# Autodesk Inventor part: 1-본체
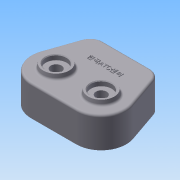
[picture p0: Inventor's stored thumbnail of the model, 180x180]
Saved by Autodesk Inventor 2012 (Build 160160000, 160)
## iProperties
Created: 2014-12
Part Number: 1-본체
Material: 알루미늄-6061
Document SubType Name: Modeling
Designer: Owner
Density: 2.71 g/cm^3
Mass: 613.304 g
Surface Area: 666.548 cm^2
Volume: 226.311 cm^3
Author: Owner
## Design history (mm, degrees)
sketch "스케치1"
  geometry: L1 (-47, 36)-(47, 36); L2 (-32.527, -32.527)-(0, 0); L3 (32.527, -32.527)-(0, 0); L4 (-32.527, -68.527)-(32.527, -68.527); L5 (-47, 36)-(-66.565, -20.803); L6 (47, 36)-(66.565, -20.803); A1 r 46 centre (0, 0) between (-32.527, -32.527) and (32.527, -32.527); A2 r 36 centre (-32.527, -32.527) between (-32.527, -68.527) and (-66.565, -20.803); A3 r 36 centre (32.527, -32.527) between (32.527, -68.527) and (66.565, -20.803); 2 further points
  constraints: 12 end point, 6 point on circle, 3 centre point, 3 tangent, 1 coincident, 1 equal radius, 1 horizontal, 1 horizontal alignment, 1 midpoint, 1 parallel, 1 vertical alignment
  dimensions: "d0" = 46 radius of A1; "d1" = 94 distance of L1.start L1.end; "d2" = 36 vertical distance of point (0, 0) L1.end; "d3" = 36 radius of A2; "d4" = 90 deg angle of L3 L2
extrude "돌출1" new body sketch "스케치1" distance "d5" = 44; taper "d6" = 0 deg
sketch "스케치2"
  geometry: C1 r 20 at (-32.527, -32.527); C2 r 20 at (32.527, -32.527); A1 r 36 centre (32.527, -32.527) between (32.527, -68.527) and (66.565, -20.803) reference; A2 r 36 centre (-32.527, -32.527) between (-66.565, -20.803) and (-32.527, -68.527) reference; 1 further point
  constraints: 2 centre point, 2 coincident, 1 equal radius
  dimensions: "d7" = 40 diameter of C2
extrude "돌출2" join sketch "스케치2" distance "d8" = 7; taper "d9" = -10 deg
sketch "스케치3"
  geometry: L1 (47, 36)-(66.565, -20.803) reference; L2 (-47, 36)-(47, 36) reference; L3 (-66.565, -20.803)-(-47, 36) reference; L4 (32.527, -68.527)-(-32.527, -68.527) reference; L5 (-43.434, 31)-(43.434, 31); L6 (43.434, 31)-(61.837, -22.432); L7 (-43.434, 31)-(-61.837, -22.432); L8 (-32.527, -63.527)-(32.527, -63.527); A1 r 36 centre (32.527, -32.527) between (32.527, -68.527) and (66.565, -20.803) reference; A2 r 36 centre (-32.527, -32.527) between (-66.565, -20.803) and (-32.527, -68.527) reference; A3 r 31 centre (-32.527, -32.527) between (-61.837, -22.432) and (-32.527, -63.527); A4 r 31 centre (32.527, -32.527) between (32.527, -63.527) and (61.837, -22.432); 1 further point
  constraints: 8 end point, 4 point on circle, 4 tangent, 3 parallel, 2 centre point, 2 coincident, 1 equal radius
  dimensions: "d10" = 31 radius of A3; "d12" = 5 distance between parallel lines of L2 L5
extrude "돌출3" cut sketch "스케치3" distance "d13" = 34; taper "d14" = 0 deg
sketch "스케치4"
  geometry: C1 r 24 at (0, 0); C2 r 24 at (-32.527, -32.527); C3 r 24 at (32.527, -32.527); A1 r 31 centre (-32.527, -32.527) between (-61.837, -22.432) and (-32.527, -63.527) reference; A2 r 31 centre (32.527, -32.527) between (32.527, -63.527) and (61.837, -22.432) reference; 1 further point
  constraints: 3 centre point, 3 coincident, 2 equal radius
  dimensions: "d15" = 48 diameter of C1
extrude "돌출4" join sketch "스케치4" distance "d16" = 11; taper "d17" = 0 deg
hole "구멍1" diameter "d20" = 15.5; stored, may be unused: countersink angle "d24" = 90 deg, drill point angle "d26" = 118 deg; dims "d18" = 10, "d19" = 10, "d21" = 6, "d22" = 30, "d23" = 7, "d25" = 8
hole "구멍2" diameter "d29" = 15.5; stored, may be unused: countersink angle "d33" = 90 deg, drill point angle "d35" = 118 deg; dims "d27" = 10, "d28" = 10, "d30" = 6, "d31" = 30, "d32" = 7, "d34" = 8
hole "구멍3" diameter "d38" = 20; stored, may be unused: countersink angle "d42" = 90 deg, drill point angle "d44" = 0 deg; dims "d39" = 6, "d40" = 40, "d41" = 12, "d43" = 15, "d45" = 10, "d46" = 10
hole "구멍4" diameter "d49" = 35; stored, may be unused: countersink angle "d53" = 90 deg, drill point angle "d55" = 0 deg; dims "d47" = 10, "d48" = 10, "d50" = 6, "d51" = 30, "d52" = 7, "d54" = 11
hole "구멍5" diameter "d58" = 35; stored, may be unused: countersink angle "d62" = 90 deg, drill point angle "d64" = 0 deg; dims "d56" = 10, "d57" = 10, "d59" = 6, "d60" = 30, "d61" = 7, "d63" = 11
sketch "스케치5"
  geometry: L1 (-47, 36)-(47, 36) reference; 2 further points
  constraints: 1 vertical alignment, 1 other
  dimensions: "d65" = 30 distance from line of L1 point (0, 6)
feature "엠보싱1" sketch "스케치5" dims "d0" = 46, "d1" = 94, "d2" = 36, "d3" = 36, "d4" = 90 deg, "d66" = 1, "d67" = 0
fillet "모깎기1" dims "d68" = 18, "d80" = 0.1, "d81" = 0.3, "d86" = 13
sketch "스케치6"
  geometry: L1 (-34.162, 36)-(34.162, 36) reference; L2 (-61.837, -22.432)-(-43.434, 31) reference; L3 (43.434, 31)-(61.837, -22.432) reference; L4 (32.527, -63.527)-(-32.527, -63.527) reference; A1 r 8 centre (51.7, 7) between (49.095, 14.564) and (54.305, -0.564); A2 r 8 centre (-51.7, 7) between (-54.305, -0.564) and (-49.095, 14.564); A3 r 8 centre (0, -63.527) between (8, -63.527) and (-8, -63.527); 1 further point
  constraints: 8 point on line, 6 point on circle, 3 centre point, 2 equal radius, 1 horizontal alignment, 1 midpoint
  dimensions: "d69" = 8 radius of A1; "d70" = 29 distance from line of L1 A1.centre
extrude "돌출5" join sketch "스케치6" stored distance "d71" = 11; taper "d72" = 0 deg
sketch "스케치7"
  geometry: A1 r 8 centre (-51.7, 7) between (-54.305, -0.564) and (-49.095, 14.564) reference; A2 r 8 centre (51.7, 7) between (49.095, 14.564) and (54.305, -0.564) reference; A3 r 8 centre (0, -63.527) between (8, -63.527) and (-8, -63.527) reference; 4 further points
  constraints: 3 coincident
hole "구멍6" sketch "스케치7" at (-51.7, 7), (51.7, 7), (0, -63.527) diameter "d73" = 4.134; stored, may be unused: countersink angle "d77" = 90 deg, drill point angle "d79" = 118 deg; dims "d74" = 20, "d75" = 30, "d76" = 7, "d78" = 23
chamfer "모따기1" distance "d82" = 1; stored, may be unused: second distance "d83" = 2, angle "d84" = 45 deg
fillet "모깎기2" dims "d85" = 3
node "솔리드1"
